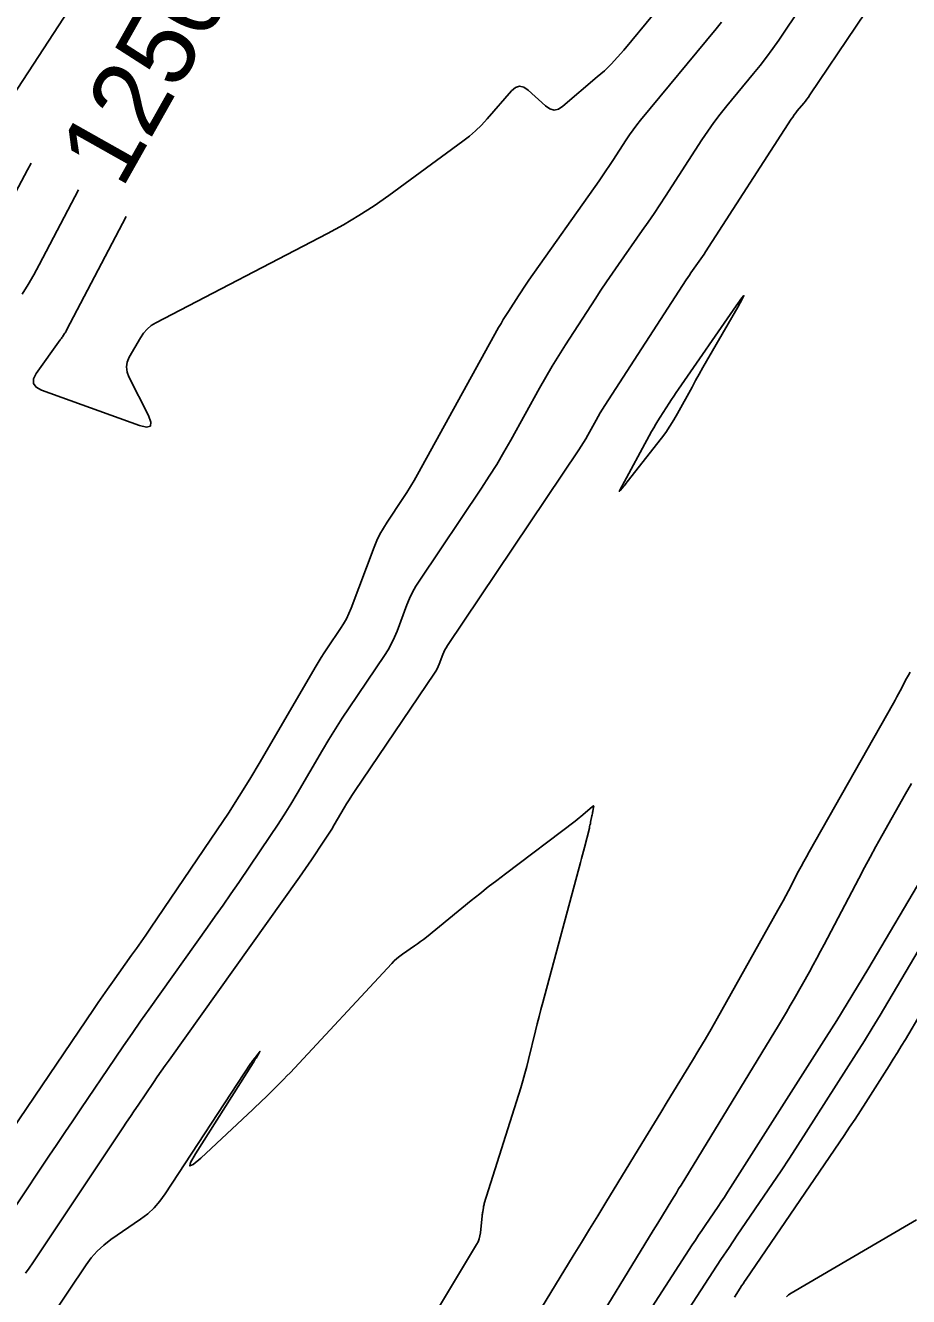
# Model space of a CAD drawing. Extents: x 658976 to 668726, y 639543 to 647196.
# Drawn here: x 661989.7 to 662059.7, y 641632.4 to 641733.2 of the extents above; entities that cross this region are included whole.
import ezdxf

# ---------------------------------------------------------------- set-up
doc = ezdxf.new("R2010")
doc.units = 0
for name, color, linetype in [('Ex_Contour Labels', 7, 'Continuous'), ('Ex_Major Contours', 7, 'Continuous'), ('Ex_Minor Contours', 7, 'Continuous')]:
    doc.layers.add(name, color=color, linetype=linetype)

msp = doc.modelspace()

# ---------------------------------------------------------------- linework, layer by layer
at = {"layer": 'Ex_Major Contours'}
for points in [[(661988.08, 641644.83), (661995.11, 641655.21), (661995.48, 641655.75), (661995.85, 641656.29), (661996.23, 641656.83), (661996.61, 641657.36), (661998.13, 641659.5), (661998.51, 641660.04), (661998.89, 641660.57), (661999.26, 641661.11), (661999.63, 641661.65), (662004.92, 641669.44), (662005.81, 641670.77), (662006.67, 641672.11), (662007.51, 641673.47), (662008.33, 641674.84), (662012.69, 641682.32), (662012.92, 641682.71), (662013.16, 641683.1), (662013.41, 641683.49), (662013.67, 641683.87), (662014.7, 641685.4), (662014.94, 641685.79), (662015.16, 641686.18), (662015.36, 641686.6), (662015.54, 641687.02), (662017.36, 641691.86), (662017.57, 641692.38), (662017.81, 641692.88), (662018.09, 641693.37), (662018.38, 641693.85), (662019.64, 641695.71), (662019.95, 641696.18), (662020.24, 641696.66), (662020.53, 641697.14), (662020.81, 641697.63), (662027.23, 641709.26), (662027.42, 641709.58), (662027.6, 641709.9), (662027.8, 641710.22), (662028, 641710.53), (662028.8, 641711.78), (662029.01, 641712.09), (662029.21, 641712.4), (662029.42, 641712.7), (662029.63, 641713.01), (662035.19, 641720.9), (662035.47, 641721.3), (662035.74, 641721.7), (662036.01, 641722.11), (662036.28, 641722.51), (662037.33, 641724.15), (662037.6, 641724.55), (662037.89, 641724.95), (662038.18, 641725.33), (662038.48, 641725.71), (662044.47, 641732.96), (662044.89, 641733.48)], [(661993.93, 641720.19), (661990.81, 641714.23), (661990.38, 641713.44), (661989.94, 641712.67), (661989.47, 641711.91)], [(662061.13, 641666.21), (662056.49, 641658.37), (662055.68, 641657.02), (662054.86, 641655.67), (662054.03, 641654.34), (662053.19, 641653), (662045.62, 641641.1), (662045.38, 641640.72), (662045.13, 641640.33), (662044.87, 641639.95), (662044.62, 641639.58), (662043.59, 641638.07), (662043.33, 641637.69), (662043.08, 641637.31), (662042.83, 641636.93), (662042.58, 641636.54), (662034.87, 641624.62)]]:
    msp.add_lwpolyline(points, dxfattribs=at)
at = {"layer": 'Ex_Minor Contours'}
for points in [[(662059.25, 641738.63), (662051.9, 641727.71), (662051.79, 641727.54), (662051.67, 641727.38), (662051.55, 641727.22), (662051.42, 641727.06), (662050.9, 641726.44), (662050.78, 641726.28), (662050.66, 641726.12), (662050.54, 641725.95), (662050.43, 641725.78), (662043.63, 641715.28), (662043.51, 641715.09), (662043.38, 641714.9), (662043.25, 641714.71), (662043.12, 641714.53), (662042.6, 641713.79), (662042.47, 641713.6), (662042.35, 641713.41), (662042.22, 641713.23), (662042.1, 641713.04), (662035.65, 641703.09), (662035.47, 641702.8), (662035.29, 641702.51), (662035.12, 641702.22), (662034.96, 641701.92), (662034.3, 641700.74), (662034.13, 641700.44), (662033.96, 641700.15), (662033.78, 641699.87), (662033.59, 641699.58), (662023.17, 641684.05), (662023.07, 641683.88), (662022.97, 641683.71), (662022.88, 641683.52), (662022.8, 641683.34), (662022.52, 641682.58), (662022.44, 641682.39), (662022.36, 641682.21), (662022.26, 641682.04), (662022.15, 641681.87), (662015.8, 641672.49), (662015.59, 641672.16), (662015.38, 641671.84), (662015.18, 641671.51), (662014.98, 641671.18), (662014.2, 641669.84), (662014, 641669.51), (662013.8, 641669.18), (662013.59, 641668.86), (662013.38, 641668.54), (662012.39, 641667.08), (662012.15, 641666.74), (662011.91, 641666.39), (662011.67, 641666.05), (662011.43, 641665.7), (662001.1, 641651.2), (662000.79, 641650.76), (662000.48, 641650.31), (662000.17, 641649.87), (661999.86, 641649.42), (661998.65, 641647.62), (661998.34, 641647.17), (661998.04, 641646.72), (661997.74, 641646.27), (661997.43, 641645.82), (661990.29, 641635.12), (661990, 641634.71), (661989.71, 641634.3)], [(662053.15, 641737.6), (662049.43, 641732.06), (662048.96, 641731.38), (662048.47, 641730.71), (662047.96, 641730.05), (662047.44, 641729.4), (662045.32, 641726.83), (662044.79, 641726.18), (662044.29, 641725.51), (662043.81, 641724.84), (662043.35, 641724.14), (662040.46, 641719.68), (662040.01, 641718.99), (662039.55, 641718.31), (662039.09, 641717.63), (662038.62, 641716.95), (662036.72, 641714.26), (662036.25, 641713.58), (662035.79, 641712.9), (662035.33, 641712.22), (662034.88, 641711.53), (662032.52, 641707.89), (662031.99, 641707.05), (662031.47, 641706.2), (662030.96, 641705.34), (662030.47, 641704.47), (662028.2, 641700.35), (662027.65, 641699.38), (662027.08, 641698.42), (662026.49, 641697.48), (662025.87, 641696.54), (662020.97, 641689.23), (662020.67, 641688.76), (662020.41, 641688.28), (662020.17, 641687.79), (662019.96, 641687.28), (662019.18, 641685.21), (662018.97, 641684.71), (662018.74, 641684.21), (662018.47, 641683.73), (662018.18, 641683.27), (662015.37, 641679.12), (662014.82, 641678.3), (662014.29, 641677.46), (662013.77, 641676.62), (662013.26, 641675.77), (662011.26, 641672.34), (662010.76, 641671.49), (662010.24, 641670.65), (662009.7, 641669.81), (662009.15, 641668.99), (662006.62, 641665.27), (662006.01, 641664.37), (662005.39, 641663.48), (662004.77, 641662.6), (662004.15, 641661.72), (661999.53, 641655.24), (661998.85, 641654.27), (661998.17, 641653.3), (661997.5, 641652.32), (661996.83, 641651.34), (661994.11, 641647.32), (661993.47, 641646.39), (661992.84, 641645.45), (661992.21, 641644.51), (661991.58, 641643.57), (661988.9, 641639.55)], [(661997.7, 641718.07), (661992.98, 641709.06), (661992.95, 641708.99), (661992.91, 641708.93), (661992.87, 641708.86), (661992.82, 641708.8), (661992.65, 641708.54), (661992.61, 641708.48), (661992.57, 641708.41), (661992.52, 641708.35), (661992.48, 641708.28), (661990.58, 641705.63), (661990.36, 641705.2), (661990.36, 641704.83), (661990.57, 641704.54), (661990.99, 641704.31), (661998.77, 641701.5), (661999.32, 641701.37), (661999.62, 641701.46), (661999.67, 641701.77), (661999.47, 641702.3), (661997.92, 641705.35), (661997.77, 641705.74), (661997.73, 641706.14), (661997.79, 641706.53), (661997.95, 641706.91), (661998.83, 641708.46), (661999.07, 641708.83), (661999.36, 641709.15), (661999.69, 641709.42), (662000.06, 641709.65), (662013.66, 641716.73), (662014.92, 641717.41), (662016.15, 641718.15), (662017.35, 641718.92), (662018.52, 641719.74), (662024.4, 641724.05), (662024.92, 641724.45), (662025.4, 641724.87), (662025.87, 641725.32), (662026.31, 641725.8), (662028.26, 641728.02), (662028.57, 641728.29), (662028.89, 641728.39), (662029.22, 641728.32), (662029.56, 641728.09), (662030.94, 641726.83), (662031.28, 641726.6), (662031.63, 641726.51), (662031.98, 641726.59), (662032.33, 641726.81), (662035.05, 641729.13), (662035.61, 641729.63), (662036.15, 641730.15), (662036.66, 641730.69), (662037.15, 641731.26), (662041.97, 641737.09)], [(661985.87, 641723.3), (661993.97, 641735.73)], [(661987.99, 641718.17), (661989.87, 641721.77), (661990.17, 641722.31)], [(662029.97, 641630.46), (662033.15, 641635.69), (662033.8, 641636.74), (662034.44, 641637.8), (662035.08, 641638.85), (662035.73, 641639.9), (662038.58, 641644.58), (662039.08, 641645.41), (662039.58, 641646.23), (662040.09, 641647.05), (662040.59, 641647.88), (662042.6, 641651.17), (662043.1, 641652), (662043.59, 641652.83), (662044.07, 641653.66), (662044.55, 641654.5), (662049.37, 641663.07), (662049.58, 641663.45), (662049.79, 641663.83), (662050, 641664.22), (662050.2, 641664.61), (662051.01, 641666.16), (662051.22, 641666.54), (662051.43, 641666.93), (662051.64, 641667.31), (662051.85, 641667.7), (662058.52, 641679.5), (662058.66, 641679.74), (662058.79, 641679.98), (662058.92, 641680.23), (662059.05, 641680.47), (662059.57, 641681.45), (662059.71, 641681.7), (662059.85, 641681.94)], [(662028.34, 641619.39), (662039.49, 641637.68), (662039.86, 641638.28), (662040.22, 641638.88), (662040.96, 641640.08), (662041.14, 641640.38), (662041.32, 641640.68), (662041.5, 641640.98), (662041.69, 641641.28), (662049.41, 641653.93), (662049.72, 641654.46), (662050.04, 641654.99), (662050.35, 641655.52), (662050.65, 641656.05), (662051.86, 641658.2), (662052.16, 641658.74), (662052.45, 641659.28), (662052.75, 641659.82), (662053.03, 641660.36), (662055.78, 641665.6), (662056.23, 641666.45), (662056.68, 641667.29), (662057.14, 641668.13), (662057.61, 641668.96), (662059.49, 641672.29), (662059.95, 641673.12)], [(662019.25, 641626.18), (662025.48, 641636.57), (662025.6, 641636.79), (662025.69, 641637.02), (662025.75, 641637.26), (662025.79, 641637.5), (662025.92, 641638.84), (662025.93, 641638.92), (662025.94, 641639), (662025.95, 641639.09), (662025.97, 641639.17), (662026.02, 641639.5), (662026.03, 641639.58), (662026.05, 641639.66), (662026.07, 641639.74), (662026.09, 641639.82), (662028.98, 641649), (662029.15, 641649.56), (662029.31, 641650.12), (662029.46, 641650.68), (662029.6, 641651.25), (662030.15, 641653.51), (662030.29, 641654.07), (662030.43, 641654.64), (662030.58, 641655.2), (662030.73, 641655.77), (662033.72, 641666.87), (662033.8, 641667.17), (662033.88, 641667.46), (662033.96, 641667.76), (662034.03, 641668.05), (662034.42, 641669.59), (662034.44, 641669.71), (662034.47, 641669.82), (662034.5, 641669.93), (662034.52, 641670.05), (662034.62, 641670.57), (662034.64, 641670.65), (662034.66, 641670.74), (662034.67, 641670.82), (662034.69, 641670.91), (662034.76, 641671.25), (662034.77, 641671.32), (662034.75, 641671.35), (662034.72, 641671.34), (662034.66, 641671.3), (662033.9, 641670.64), (662033.75, 641670.51), (662033.6, 641670.39), (662033.45, 641670.26), (662033.29, 641670.14), (662027.77, 641665.97), (662027.08, 641665.44), (662026.4, 641664.92), (662025.73, 641664.38), (662025.06, 641663.84), (662021.5, 641660.94), (662021.27, 641660.76), (662021.04, 641660.59), (662020.81, 641660.42), (662020.57, 641660.25), (662019.62, 641659.6), (662019.39, 641659.43), (662019.16, 641659.25), (662018.95, 641659.06), (662018.75, 641658.85), (662010.69, 641650.19), (662010.45, 641649.94), (662010.21, 641649.69), (662009.97, 641649.44), (662009.73, 641649.2), (662008.74, 641648.23), (662008.49, 641647.99), (662008.24, 641647.75), (662007.99, 641647.51), (662007.74, 641647.27), (662003.62, 641643.43), (662003.02, 641642.91), (662002.74, 641642.8), (662002.81, 641643.09), (662003.21, 641643.77), (662007.76, 641650.97), (662007.82, 641651.07), (662007.88, 641651.16), (662007.94, 641651.26), (662008, 641651.36), (662008.27, 641651.82), (662008.3, 641651.87), (662008.31, 641651.89), (662008.29, 641651.88), (662008.26, 641651.83), (662008.06, 641651.55), (662008.02, 641651.5), (662007.98, 641651.45), (662007.94, 641651.4), (662007.9, 641651.35), (662007.74, 641651.16), (662007.7, 641651.11), (662007.66, 641651.06), (662007.63, 641651.01), (662007.59, 641650.96), (662000.8, 641640.59), (662000.38, 641640.02), (661999.92, 641639.49), (661999.41, 641639.01), (661998.84, 641638.58), (661996.49, 641636.96), (661995.93, 641636.53), (661995.41, 641636.05), (661994.94, 641635.53), (661994.52, 641634.96), (661991.68, 641630.7)], [(662060.92, 641660.57), (662058.08, 641655.78), (662057.47, 641654.76), (662056.85, 641653.73), (662056.22, 641652.72), (662055.58, 641651.7), (662051.62, 641645.47), (662050.96, 641644.45), (662050.3, 641643.43), (662049.63, 641642.42), (662048.95, 641641.41), (662046.15, 641637.32), (662045.5, 641636.35), (662044.85, 641635.38), (662044.21, 641634.41), (662043.58, 641633.43), (662041.04, 641629.52)], [(662045.92, 641632.4), (662046.38, 641633.11), (662046.49, 641633.29), (662046.61, 641633.47), (662046.73, 641633.64), (662046.85, 641633.82), (662054.62, 641645.23), (662055.05, 641645.87), (662055.48, 641646.52), (662055.91, 641647.18), (662056.33, 641647.83), (662058.19, 641650.75), (662058.51, 641651.27), (662058.84, 641651.79), (662059.15, 641652.31), (662059.47, 641652.84), (662060.72, 641654.95)], [(662060.35, 641638.54), (662059.73, 641638.15), (662050.42, 641632.72), (662050.22, 641632.59), (662050.04, 641632.43)]]:
    msp.add_lwpolyline(points, dxfattribs=at)
msp.add_lwpolyline([(662041.13, 641701.94), (662040.81, 641701.44), (662040.48, 641700.96), (662040.13, 641700.49), (662037.42, 641697.03), (662037.35, 641696.94), (662037.28, 641696.86), (662037.22, 641696.77), (662037.15, 641696.69), (662036.87, 641696.36), (662036.82, 641696.3), (662036.79, 641696.28), (662036.8, 641696.31), (662036.84, 641696.38), (662039.36, 641701.03), (662039.52, 641701.31), (662039.69, 641701.6), (662039.86, 641701.88), (662040.03, 641702.16), (662040.75, 641703.28), (662040.92, 641703.56), (662041.11, 641703.83), (662041.29, 641704.11), (662041.48, 641704.38), (662046.05, 641710.98), (662046.5, 641711.61), (662046.67, 641711.8), (662046.57, 641711.56), (662046.19, 641710.89), (662043.71, 641706.6), (662043.42, 641706.09), (662043.13, 641705.57), (662042.84, 641705.06), (662042.56, 641704.54), (662041.42, 641702.46)], close=True, dxfattribs=at)

# ---------------------------------------------------------------- texts
at = {"layer": 'Ex_Contour Labels'}
msp.add_text('1250', height=6, rotation=60.6069, dxfattribs=at).set_placement((661997.36, 641720.17))

doc.saveas('drawing.dxf')
